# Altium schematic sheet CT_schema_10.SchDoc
size 287 x 160 mm
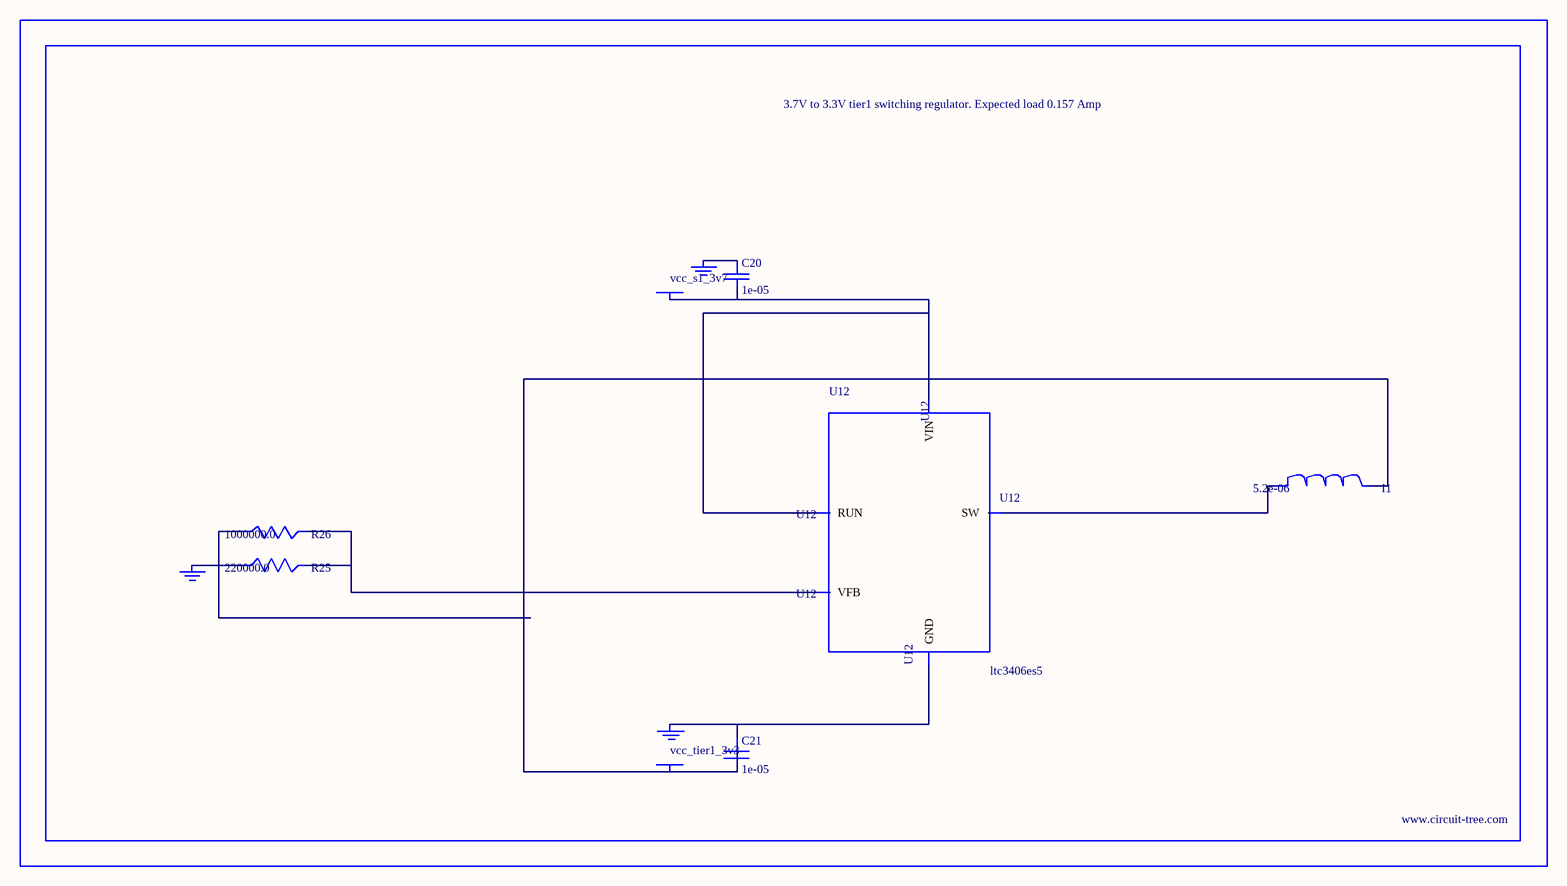
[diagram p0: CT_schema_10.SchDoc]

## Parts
BORDER9  (no value)
C20  1e-05  [C0805]
C21  1e-05  [C0805]
GND_INSTANCE_9_0  (no value)
GND_INSTANCE_9_1  (no value)
GND_INSTANCE_9_2  (no value)
I1  5.2e-06  [DR1040]
POWER_INSTANCE_9_0  vcc_tier1_3v3
POWER_INSTANCE_9_1  vcc_s1_3v7
R25  220000.0  [R0603]
R26  1000000.0  [R0603]
U12  ltc3406es5  [TSOT-23-5]

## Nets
NetC20_1: C20.1 GND_INSTANCE_9_1.0(GND)
NetC20_2: C20.2 POWER_INSTANCE_9_1.0(PWR) U12.1(RUN) U12.4(VIN)
NetC21_1: C21.1 GND_INSTANCE_9_0.0(GND) U12.2(GND)
NetC21_2: C21.2 I1.2 POWER_INSTANCE_9_0.0(PWR) R26.1
NetGND_INSTANCE_9_2_0: GND_INSTANCE_9_2.0(GND) R25.1
NetI1_1: I1.1 U12.3(SW)
NetR25_2: R25.2 R26.2 U12.5(VFB)

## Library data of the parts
BORDER9 = BORDER_PAGE9
C20 C21 = C0805C106K8RACTU
GND_INSTANCE_9_0-GND_INSTANCE_9_2 = GND
I1 = DR1040-5R2-R
POWER_INSTANCE_9_0 POWER_INSTANCE_9_1 = PWR
R25 = RC0603JR-07220KL
R26 = RC0603JR-071ML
